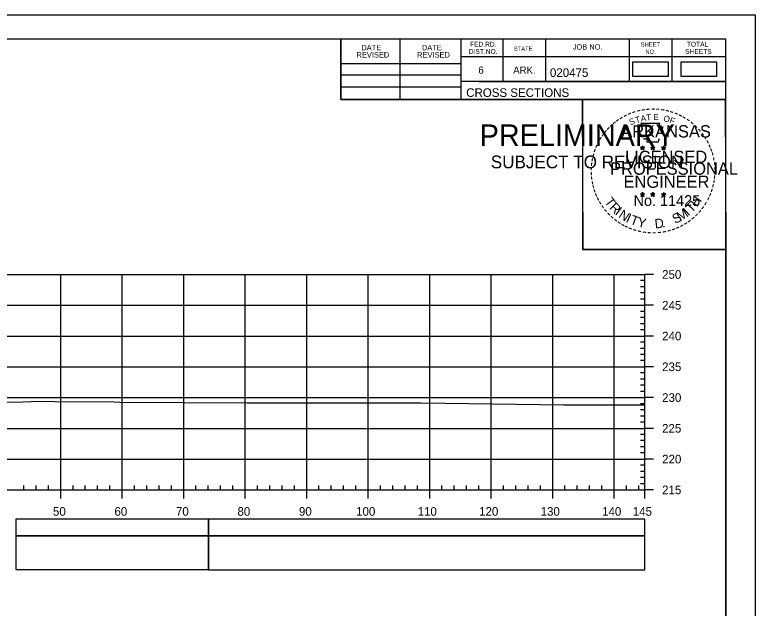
# Model space of a CAD drawing. Extents: x 1386544 to 1388153, y 379785 to 390999.
# Drawn here: x 1386757.4 to 1386877.8, y 384182.2 to 384278.6 of the extents above; entities that cross this region are included whole.
import ezdxf

# ---------------------------------------------------------------- set-up
doc = ezdxf.new("R2010")
doc.units = 0
for name, color, linetype in [('R_Axis', 7, 'Continuous'), ('R_Axis Annot', 7, 'Continuous'), ('R_Border', 7, 'Continuous'), ('R_Border PE', 7, 'Continuous'), ('R_Border Prem', 7, 'Continuous'), ('R_Exist Surface', 7, 'Continuous'), ('R_Grid', 7, 'Continuous'), ('R_No Plot', 7, 'Continuous'), ('R_Striping', 7, 'Continuous'), ('S_SHOULDER', 7, 'Continuous')]:
    doc.layers.add(name, color=color, linetype=linetype)

msp = doc.modelspace()

# ---------------------------------------------------------------- linework, layer by layer
at = {"layer": 'R_Axis'}
for p, q in [((1386859.87, 384201.41), (1386859.87, 384236.41)), ((1386861.27, 384236.41), (1386859.87, 384236.41)), ((1386859.87, 384235.41), (1386859.17, 384235.41)), ((1386859.87, 384234.41), (1386859.17, 384234.41)), ((1386859.87, 384233.41), (1386859.17, 384233.41)), ((1386859.87, 384232.41), (1386859.17, 384232.41)), ((1386861.27, 384231.41), (1386859.87, 384231.41)), ((1386859.87, 384230.41), (1386859.17, 384230.41)), ((1386859.87, 384229.41), (1386859.17, 384229.41)), ((1386859.87, 384228.41), (1386859.17, 384228.41)), ((1386859.87, 384227.41), (1386859.17, 384227.41)), ((1386861.27, 384226.41), (1386859.87, 384226.41)), ((1386859.87, 384225.41), (1386859.17, 384225.41)), ((1386859.87, 384224.41), (1386859.17, 384224.41)), ((1386859.87, 384223.41), (1386859.17, 384223.41)), ((1386859.87, 384222.41), (1386859.17, 384222.41)), ((1386861.27, 384221.41), (1386859.87, 384221.41)), ((1386859.87, 384220.41), (1386859.17, 384220.41)), ((1386859.87, 384219.41), (1386859.17, 384219.41)), ((1386859.87, 384218.41), (1386859.17, 384218.41)), ((1386859.87, 384217.41), (1386859.17, 384217.41)), ((1386861.27, 384216.41), (1386859.87, 384216.41)), ((1386859.87, 384215.41), (1386859.17, 384215.41)), ((1386859.87, 384214.41), (1386859.17, 384214.41)), ((1386859.87, 384213.41), (1386859.17, 384213.41)), ((1386859.87, 384212.41), (1386859.17, 384212.41)), ((1386861.27, 384211.41), (1386859.87, 384211.41)), ((1386859.87, 384210.41), (1386859.17, 384210.41)), ((1386859.87, 384209.41), (1386859.17, 384209.41)), ((1386859.87, 384208.41), (1386859.17, 384208.41)), ((1386859.87, 384207.41), (1386859.17, 384207.41)), ((1386859.87, 384205.41), (1386859.17, 384205.41)), ((1386861.27, 384206.41), (1386859.87, 384206.41)), ((1386859.87, 384204.41), (1386859.17, 384204.41)), ((1386859.87, 384203.41), (1386859.17, 384203.41)), ((1386758.87, 384201.41), (1386758.87, 384202.11)), ((1386760.87, 384201.41), (1386760.87, 384202.11)), ((1386762.87, 384201.41), (1386762.87, 384202.11)), ((1386766.87, 384201.41), (1386766.87, 384202.11)), ((1386768.87, 384201.41), (1386768.87, 384202.11)), ((1386770.87, 384201.41), (1386770.87, 384202.11)), ((1386772.87, 384201.41), (1386772.87, 384202.11)), ((1386776.87, 384201.41), (1386776.87, 384202.11)), ((1386778.87, 384201.41), (1386778.87, 384202.11)), ((1386780.87, 384201.41), (1386780.87, 384202.11)), ((1386782.87, 384201.41), (1386782.87, 384202.11)), ((1386786.87, 384201.41), (1386786.87, 384202.11)), ((1386788.87, 384201.41), (1386788.87, 384202.11)), ((1386790.87, 384201.41), (1386790.87, 384202.11)), ((1386792.87, 384201.41), (1386792.87, 384202.11)), ((1386796.87, 384201.41), (1386796.87, 384202.11)), ((1386798.87, 384201.41), (1386798.87, 384202.11)), ((1386800.87, 384201.41), (1386800.87, 384202.11)), ((1386802.87, 384201.41), (1386802.87, 384202.11)), ((1386806.87, 384201.41), (1386806.87, 384202.11)), ((1386808.87, 384201.41), (1386808.87, 384202.11)), ((1386810.87, 384201.41), (1386810.87, 384202.11)), ((1386812.87, 384201.41), (1386812.87, 384202.11)), ((1386816.87, 384201.41), (1386816.87, 384202.11)), ((1386818.87, 384201.41), (1386818.87, 384202.11)), ((1386820.87, 384201.41), (1386820.87, 384202.11)), ((1386822.87, 384201.41), (1386822.87, 384202.11)), ((1386826.87, 384201.41), (1386826.87, 384202.11)), ((1386828.87, 384201.41), (1386828.87, 384202.11)), ((1386830.87, 384201.41), (1386830.87, 384202.11)), ((1386832.87, 384201.41), (1386832.87, 384202.11)), ((1386836.87, 384201.41), (1386836.87, 384202.11)), ((1386838.87, 384201.41), (1386838.87, 384202.11)), ((1386840.87, 384201.41), (1386840.87, 384202.11)), ((1386842.87, 384201.41), (1386842.87, 384202.11)), ((1386846.87, 384201.41), (1386846.87, 384202.11)), ((1386848.87, 384201.41), (1386848.87, 384202.11)), ((1386850.87, 384201.41), (1386850.87, 384202.11)), ((1386852.87, 384201.41), (1386852.87, 384202.11)), ((1386856.87, 384201.41), (1386856.87, 384202.11)), ((1386858.87, 384201.41), (1386858.87, 384202.11)), ((1386859.87, 384202.41), (1386859.17, 384202.41)), ((1386569.87, 384201.41), (1386859.87, 384201.41)), ((1386764.87, 384200.01), (1386764.87, 384201.41)), ((1386774.87, 384200.01), (1386774.87, 384201.41)), ((1386784.87, 384200.01), (1386784.87, 384201.41)), ((1386794.87, 384200.01), (1386794.87, 384201.41)), ((1386804.87, 384200.01), (1386804.87, 384201.41)), ((1386814.87, 384200.01), (1386814.87, 384201.41)), ((1386824.87, 384200.01), (1386824.87, 384201.41)), ((1386834.87, 384200.01), (1386834.87, 384201.41)), ((1386844.87, 384200.01), (1386844.87, 384201.41)), ((1386854.87, 384200.01), (1386854.87, 384201.41)), ((1386859.87, 384200.01), (1386859.87, 384201.41)), ((1386861.27, 384201.41), (1386859.87, 384201.41))]:
    msp.add_line(p, q, dxfattribs=at)
at = {"layer": 'R_Axis Annot'}
for points in [[(1386788.89, 384193.97), (1386859.87, 384193.97), (1386859.87, 384196.68), (1386788.89, 384196.68)], [(1386788.89, 384188.44), (1386859.87, 384188.44), (1386859.87, 384193.97), (1386788.89, 384193.97)]]:
    msp.add_lwpolyline(points, close=True, dxfattribs=at)
at = {"layer": 'R_Border'}
for p, q in [((1386556.87, 384274.71), (1386873.05, 384274.71)), ((1386810.41, 384264.83), (1386810.41, 384274.71)), ((1386820.09, 384264.83), (1386820.09, 384274.71)), ((1386829.95, 384274.71), (1386829.95, 384264.83)), ((1386836.79, 384274.71), (1386836.79, 384267.77)), ((1386843.73, 384274.71), (1386843.73, 384267.77)), ((1386857.31, 384274.71), (1386857.31, 384267.77)), ((1386864.25, 384274.71), (1386864.25, 384267.77)), ((1386873.05, 384069.25), (1386873.05, 384274.71)), ((1386873.05, 384271.77), (1386829.95, 384271.77)), ((1386873.05, 384271.79), (1386873.05, 384271.79)), ((1386810.41, 384270.69), (1386829.95, 384270.69)), ((1386810.41, 384268.83), (1386829.95, 384268.83)), ((1386810.41, 384266.89), (1386829.95, 384266.89)), ((1386873.05, 384267.77), (1386829.95, 384267.77)), ((1386832.91, 384267.77), (1386873.05, 384267.77)), ((1386873.05, 384264.83), (1386810.41, 384264.83))]:
    msp.add_line(p, q, dxfattribs=at)
at = {"layer": 'R_Border PE'}
for p, q in [((1386859.48, 384257.34), (1386859.44, 384257.08)), ((1386859.48, 384256.97), (1386859.48, 384257.34)), ((1386859.48, 384257.34), (1386859.53, 384257.09)), ((1386861.15, 384257.34), (1386861.11, 384257.08)), ((1386861.15, 384256.97), (1386861.15, 384257.34)), ((1386861.15, 384257.34), (1386861.2, 384257.09)), ((1386862.92, 384257.32), (1386862.88, 384257.07)), ((1386862.92, 384256.96), (1386862.92, 384257.32)), ((1386862.92, 384257.32), (1386862.97, 384257.07)), ((1386859.14, 384257.08), (1386859.48, 384256.97)), ((1386859.14, 384257.08), (1386859.39, 384257.04)), ((1386859.14, 384257.08), (1386859.37, 384256.96)), ((1386859.27, 384256.67), (1386859.48, 384256.97)), ((1386859.27, 384256.67), (1386859.39, 384256.92)), ((1386859.27, 384256.67), (1386859.48, 384256.89)), ((1386859.83, 384257.08), (1386859.48, 384256.97)), ((1386859.7, 384256.67), (1386859.48, 384256.97)), ((1386859.7, 384256.67), (1386859.48, 384256.89)), ((1386859.83, 384257.08), (1386859.55, 384257.03)), ((1386859.7, 384256.67), (1386859.56, 384256.96)), ((1386859.83, 384257.08), (1386859.63, 384256.98)), ((1386860.81, 384257.08), (1386861.15, 384256.97)), ((1386860.81, 384257.08), (1386861.06, 384257.04)), ((1386860.81, 384257.08), (1386861.04, 384256.96)), ((1386860.94, 384256.67), (1386861.15, 384256.97)), ((1386860.94, 384256.67), (1386861.06, 384256.92)), ((1386860.94, 384256.67), (1386861.15, 384256.89)), ((1386861.5, 384257.08), (1386861.15, 384256.97)), ((1386861.37, 384256.67), (1386861.15, 384256.97)), ((1386861.37, 384256.67), (1386861.15, 384256.89)), ((1386861.5, 384257.08), (1386861.22, 384257.03)), ((1386861.37, 384256.67), (1386861.23, 384256.96)), ((1386861.5, 384257.08), (1386861.3, 384256.98)), ((1386862.57, 384257.07), (1386862.92, 384256.96)), ((1386862.57, 384257.07), (1386862.82, 384257.02)), ((1386862.57, 384257.07), (1386862.81, 384256.95)), ((1386862.7, 384256.66), (1386862.92, 384256.96)), ((1386862.7, 384256.66), (1386862.83, 384256.91)), ((1386862.7, 384256.66), (1386862.92, 384256.88)), ((1386863.27, 384257.07), (1386862.92, 384256.96)), ((1386863.13, 384256.66), (1386862.92, 384256.96)), ((1386863.13, 384256.66), (1386862.92, 384256.88)), ((1386863.27, 384257.07), (1386862.98, 384257.02)), ((1386863.13, 384256.66), (1386862.99, 384256.95)), ((1386863.27, 384257.07), (1386863.06, 384256.97)), ((1386859.13, 384249.51), (1386859.48, 384249.4)), ((1386859.13, 384249.51), (1386859.38, 384249.46)), ((1386859.13, 384249.51), (1386859.37, 384249.39)), ((1386859.26, 384249.1), (1386859.48, 384249.4)), ((1386859.26, 384249.1), (1386859.39, 384249.34)), ((1386859.26, 384249.1), (1386859.48, 384249.32)), ((1386859.48, 384249.76), (1386859.44, 384249.51)), ((1386859.48, 384249.4), (1386859.48, 384249.76)), ((1386859.48, 384249.76), (1386859.53, 384249.51)), ((1386859.83, 384249.51), (1386859.48, 384249.4)), ((1386859.69, 384249.1), (1386859.48, 384249.4)), ((1386859.69, 384249.1), (1386859.48, 384249.31)), ((1386859.83, 384249.51), (1386859.54, 384249.46)), ((1386859.69, 384249.1), (1386859.56, 384249.39)), ((1386859.83, 384249.51), (1386859.62, 384249.41)), ((1386860.8, 384249.51), (1386861.15, 384249.4)), ((1386860.8, 384249.51), (1386861.05, 384249.46)), ((1386860.8, 384249.51), (1386861.04, 384249.39)), ((1386860.93, 384249.1), (1386861.15, 384249.4)), ((1386860.93, 384249.1), (1386861.06, 384249.34)), ((1386860.93, 384249.1), (1386861.15, 384249.32)), ((1386861.15, 384249.76), (1386861.11, 384249.51)), ((1386861.15, 384249.4), (1386861.15, 384249.76)), ((1386861.15, 384249.76), (1386861.2, 384249.51)), ((1386861.5, 384249.51), (1386861.15, 384249.4)), ((1386861.36, 384249.1), (1386861.15, 384249.4)), ((1386861.36, 384249.1), (1386861.15, 384249.31)), ((1386861.5, 384249.51), (1386861.21, 384249.46)), ((1386861.36, 384249.1), (1386861.23, 384249.39)), ((1386861.5, 384249.51), (1386861.29, 384249.41)), ((1386862.57, 384249.5), (1386862.92, 384249.39)), ((1386862.57, 384249.5), (1386862.82, 384249.45)), ((1386862.57, 384249.5), (1386862.8, 384249.38)), ((1386862.7, 384249.09), (1386862.92, 384249.39)), ((1386862.7, 384249.09), (1386862.83, 384249.33)), ((1386862.7, 384249.09), (1386862.91, 384249.31)), ((1386862.92, 384249.75), (1386862.88, 384249.5)), ((1386863.13, 384249.09), (1386862.91, 384249.3)), ((1386862.92, 384249.39), (1386862.92, 384249.75)), ((1386862.92, 384249.75), (1386862.97, 384249.5)), ((1386863.26, 384249.5), (1386862.92, 384249.39)), ((1386863.13, 384249.09), (1386862.92, 384249.39)), ((1386863.26, 384249.5), (1386862.98, 384249.45)), ((1386863.13, 384249.09), (1386862.99, 384249.38)), ((1386863.26, 384249.5), (1386863.06, 384249.4))]:
    msp.add_line(p, q, dxfattribs=at)
for points in [[(1386859.18, 384260.96), (1386859.45, 384260.13)], [(1386862.69, 384260.04), (1386862.83, 384260.32), (1386862.14, 384260.3), (1386862.29, 384260.96), (1386859.18, 384260.96)], [(1386859.67, 384258.54), (1386859.67, 384258.45), (1386860.23, 384258.43), (1386860.18, 384257.96), (1386862.05, 384257.96), (1386862.25, 384258.49)], [(1386859.48, 384257.34), (1386859.7, 384256.67), (1386859.14, 384257.08), (1386859.83, 384257.08), (1386859.27, 384256.67), (1386859.48, 384257.34)], [(1386861.15, 384257.34), (1386861.37, 384256.67), (1386860.81, 384257.08), (1386861.5, 384257.08), (1386860.94, 384256.67), (1386861.15, 384257.34)], [(1386862.92, 384257.32), (1386863.13, 384256.66), (1386862.57, 384257.07), (1386863.27, 384257.07), (1386862.7, 384256.66), (1386862.92, 384257.32)], [(1386859.48, 384249.76), (1386859.69, 384249.1), (1386859.13, 384249.51), (1386859.83, 384249.51), (1386859.26, 384249.1), (1386859.48, 384249.76)], [(1386861.15, 384249.76), (1386861.36, 384249.1), (1386860.8, 384249.51), (1386861.5, 384249.51), (1386860.93, 384249.1), (1386861.15, 384249.76)], [(1386862.92, 384249.75), (1386863.13, 384249.09), (1386862.57, 384249.5), (1386863.26, 384249.5), (1386862.7, 384249.09), (1386862.92, 384249.75)]]:
    msp.add_lwpolyline(points, dxfattribs=at)
for centre, radius in [((1386859.48, 384256.97), 0.172), ((1386859.48, 384256.97), 0.145), ((1386861.15, 384256.97), 0.172), ((1386861.15, 384256.97), 0.145), ((1386862.92, 384256.96), 0.172), ((1386859.48, 384256.97), 0.116), ((1386859.48, 384256.97), 0.0991), ((1386859.48, 384256.97), 0.0747), ((1386859.48, 384256.97), 0.0495), ((1386859.48, 384256.97), 0.0296), ((1386861.15, 384256.97), 0.116), ((1386861.15, 384256.97), 0.0991), ((1386861.15, 384256.97), 0.0747), ((1386861.15, 384256.97), 0.0495), ((1386861.15, 384256.97), 0.0296), ((1386862.92, 384256.96), 0.145), ((1386862.92, 384256.96), 0.116), ((1386862.92, 384256.96), 0.0991), ((1386862.92, 384256.96), 0.0747), ((1386862.92, 384256.96), 0.0495), ((1386862.92, 384256.96), 0.0296), ((1386859.48, 384249.4), 0.172), ((1386859.48, 384249.4), 0.145), ((1386859.48, 384249.4), 0.116), ((1386859.48, 384249.4), 0.0991), ((1386859.48, 384249.4), 0.0747), ((1386859.48, 384249.4), 0.0495), ((1386859.48, 384249.4), 0.0296), ((1386861.15, 384249.4), 0.172), ((1386861.15, 384249.4), 0.145), ((1386861.15, 384249.4), 0.116), ((1386861.15, 384249.4), 0.0991), ((1386861.15, 384249.4), 0.0747), ((1386861.15, 384249.4), 0.0495), ((1386861.15, 384249.4), 0.0296), ((1386862.92, 384249.39), 0.172), ((1386862.92, 384249.39), 0.145), ((1386862.92, 384249.39), 0.116), ((1386862.92, 384249.39), 0.0991), ((1386862.92, 384249.39), 0.0747), ((1386862.92, 384249.39), 0.0495), ((1386862.92, 384249.39), 0.0296)]:
    msp.add_circle(centre, radius, dxfattribs=at)
at = {"layer": 'R_Exist Surface'}
msp.add_lwpolyline([(1386750.38, 384215.56), (1386758.7, 384215.74), (1386761.41, 384215.8), (1386763.89, 384215.79), (1386773.59, 384215.7), (1386774.5, 384215.68), (1386795.26, 384215.58), (1386812.09, 384215.56), (1386816.68, 384215.57), (1386823.44, 384215.54), (1386846.67, 384215.25), (1386852.54, 384215.24), (1386859.87, 384215.25)], dxfattribs=at)
at = {"layer": 'R_Grid'}
for p, q in [((1386569.87, 384236.41), (1386859.87, 384236.41)), ((1386764.87, 384201.41), (1386764.87, 384236.41)), ((1386774.87, 384201.41), (1386774.87, 384236.41)), ((1386784.87, 384201.41), (1386784.87, 384236.41)), ((1386794.87, 384201.41), (1386794.87, 384236.41)), ((1386804.87, 384201.41), (1386804.87, 384236.41)), ((1386814.87, 384201.41), (1386814.87, 384236.41)), ((1386824.87, 384201.41), (1386824.87, 384236.41)), ((1386834.87, 384201.41), (1386834.87, 384236.41)), ((1386844.87, 384201.41), (1386844.87, 384236.41)), ((1386854.87, 384201.41), (1386854.87, 384236.41)), ((1386859.87, 384201.41), (1386859.87, 384236.41)), ((1386569.87, 384231.41), (1386859.87, 384231.41)), ((1386569.87, 384226.41), (1386859.87, 384226.41)), ((1386569.87, 384221.41), (1386859.87, 384221.41)), ((1386569.87, 384216.41), (1386859.87, 384216.41)), ((1386569.87, 384211.41), (1386859.87, 384211.41)), ((1386569.87, 384206.41), (1386859.87, 384206.41)), ((1386569.87, 384201.41), (1386859.87, 384201.41))]:
    msp.add_line(p, q, dxfattribs=at)
at = {"layer": 'R_No Plot'}
for p, q in [((1386544.47, 384278.6), (1386877.8, 384278.6)), ((1386849.08, 384242.37), (1386849.08, 384242.37))]:
    msp.add_line(p, q, dxfattribs=at)
for points in [[(1386544.46, 384278.6), (1386877.8, 384278.6), (1386877.8, 384065.26), (1386544.46, 384065.26)], [(1386790.79, 384274.71), (1386810.41, 384274.71), (1386810.41, 384264.83), (1386826.52, 384264.83), (1386849.72, 384264.83), (1386849.72, 384240.49), (1386873.05, 384240.49), (1386873.05, 384069.25), (1386556.87, 384069.25), (1386556.87, 384274.71)], [(1386849.72, 384264.83), (1386872.93, 384264.83), (1386873.05, 384240.49), (1386849.84, 384240.49)]]:
    msp.add_lwpolyline(points, close=True, dxfattribs=at)
at = {"layer": 'R_Striping'}
for points in [[(1386757.55, 384193.97), (1386788.89, 384193.97), (1386788.89, 384196.68), (1386757.55, 384196.68)], [(1386757.55, 384188.45), (1386788.89, 384188.45), (1386788.89, 384193.97), (1386757.55, 384193.97)]]:
    msp.add_lwpolyline(points, close=True, dxfattribs=at)
at = {"layer": 'S_SHOULDER'}
for points in [[(1386857.86, 384268.61), (1386863.7, 384268.61), (1386863.7, 384270.92), (1386857.86, 384270.92)], [(1386865.73, 384268.61), (1386871.57, 384268.61), (1386871.57, 384270.92), (1386865.73, 384270.92)]]:
    msp.add_lwpolyline(points, close=True, dxfattribs=at)

# ---------------------------------------------------------------- texts
at = {"layer": 'R_Axis Annot'}
for s, p in [('250', (1386862.67, 384235.71)), ('245', (1386862.67, 384230.71)), ('240', (1386862.67, 384225.71)), ('235', (1386862.67, 384220.71)), ('230', (1386862.67, 384215.71)), ('225', (1386862.67, 384210.71)), ('220', (1386862.67, 384205.71)), ('215', (1386862.67, 384200.71)), ('50', (1386763.61, 384197.21)), ('60', (1386773.61, 384197.21)), ('70', (1386783.61, 384197.21)), ('80', (1386793.61, 384197.21)), ('90', (1386803.61, 384197.21)), ('100', (1386812.91, 384197.21)), ('110', (1386822.91, 384197.21)), ('120', (1386832.91, 384197.21)), ('130', (1386842.91, 384197.21)), ('140', (1386852.91, 384197.21)), ('145', (1386857.9, 384197.21))]:
    msp.add_text(s, height=1.4, dxfattribs=at).set_placement(p)
at = {"layer": 'R_Border'}
for s, height, p in [('FED.RD.', 0.782, (1386831.43, 384273.43)), ('SHEET', 0.684, (1386859.17, 384273.43)), ('TOTAL', 0.782, (1386866.69, 384273.43)), ('DATE', 0.879, (1386813.75, 384272.84)), ('DATE', 0.879, (1386823.61, 384272.84)), ('DIST.NO.', 0.782, (1386831.23, 384272.25)), ('STATE', 0.684, (1386838.55, 384272.75)), ('JOB NO.', 0.879, (1386848.13, 384272.95)), ('NO.', 0.684, (1386859.95, 384272.25)), ('SHEETS', 0.782, (1386866.41, 384272.25)), ('REVISED', 0.879, (1386812.97, 384271.66)), ('REVISED', 0.879, (1386822.83, 384271.66)), ('6', 1.17, (1386832.79, 384269.03)), ('ARK.', 1.172, (1386838.45, 384269.03)), ('020475', 1.4, (1386844.43, 384268.51)), ('CROSS SECTIONS', 1.4, (1386830.81, 384265.26))]:
    msp.add_text(s, height=height, rotation=360, dxfattribs=at).set_placement(p)
at = {"layer": 'R_Border PE'}
for s, height, rotation, p in [('-', 1.6, 13.6301, (1386858.67, 384262.33)), ('-', 1.6, 10.2193, (1386859.35, 384262.49)), ('-', 1.6, 5.8968, (1386860.08, 384262.6)), ('-', 1.6, 0.1862, (1386860.85, 384262.67)), ('-', 1.6, 357.743, (1386861.58, 384262.66)), ('-', 1.6, 352.1617, (1386862.32, 384262.6)), ('-', 1.6, 347.2049, (1386863.04, 384262.49)), ('-', 1.6, 34.0636, (1386856.06, 384261.13)), ('-', 1.6, 28.7918, (1386856.66, 384261.5)), ('-', 1.6, 24.3072, (1386857.29, 384261.82)), ('-', 1.6, 19.1761, (1386857.92, 384262.09)), ('T', 1, 16.4036, (1386858.45, 384260.97)), ('A', 1, 11.2132, (1386859.27, 384261.22)), ('T', 1, 6.0228, (1386860.12, 384261.39)), ('E', 1, 0.8323, (1386861.23, 384261.5)), ('O', 1, 350.4515, (1386862.83, 384261.29)), ('F', 1, 340.0707, (1386863.78, 384261.06)), ('-', 1.6, 342.3362, (1386863.67, 384262.33)), ('-', 1.6, 337.8551, (1386864.41, 384262.11)), ('-', 1.6, 334.1211, (1386865.04, 384261.84)), ('-', 1.6, 329.6409, (1386865.62, 384261.56)), ('-', 1.6, 42.9622, (1386854.57, 384259.94)), ('-', 1.6, 38.9507, (1386855.01, 384260.36)), ('-', 1.6, 36.2317, (1386855.48, 384260.74)), ('S', 1, 21.594, (1386857.53, 384260.64)), ('-', 1.6, 325.8627, (1386866.26, 384261.2)), ('-', 1.6, 320.5297, (1386866.87, 384260.77)), ('-', 1.6, 50.6142, (1386853.72, 384258.98)), ('-', 1.6, 48.423, (1386854.13, 384259.46)), ('ARKANSAS', 2, 360, (1386856.03, 384258.67)), ('-', 1.6, 315.5786, (1386867.47, 384260.28)), ('-', 1.6, 309.8797, (1386868.04, 384259.73)), ('-', 1.6, 58.0706, (1386852.98, 384257.88)), ('-', 1.6, 54.2325, (1386853.31, 384258.41)), ('-', 1.6, 306.6522, (1386868.57, 384259.13)), ('-', 1.4, 303.6753, (1386869.05, 384258.56)), ('-', 1.6, 67.7743, (1386852.41, 384256.66)), ('-', 1.6, 62.8713, (1386852.67, 384257.27)), ('-', 1.6, 299.6684, (1386869.37, 384257.95)), ('-', 1.6, 294.6628, (1386869.69, 384257.34)), ('-', 1.6, 75.461, (1386852, 384255.31)), ('-', 1.6, 72.3945, (1386852.19, 384256.03)), ('LICENSED', 2, 360, (1386856.63, 384254.52)), ('DWB', 0.01, 360, (1386859.47, 384256.97)), ('DWB', 0.01, 360, (1386861.14, 384256.97)), ('DWB', 0.01, 360, (1386862.91, 384256.95)), ('-', 1.6, 290.5728, (1386869.95, 384256.77)), ('-', 1.6, 285.1233, (1386870.19, 384256.19)), ('-', 1.6, 81.2013, (1386851.86, 384254.6)), ('-', 1.6, 280.5493, (1386870.39, 384255.44)), ('-', 1.6, 89.0622, (1386851.76, 384253.21)), ('-', 1.6, 85.1863, (1386851.79, 384253.91)), ('PROFESSIONAL', 2, 360, (1386854.2, 384252.62)), ('-', 1.6, 276.5962, (1386870.55, 384254.68)), ('-', 1.6, 274.3301, (1386870.61, 384253.95)), ('-', 1.6, 94.1959, (1386851.8, 384252.48)), ('-', 1.6, 98.9479, (1386851.87, 384251.82)), ('ENGINEER', 2, 360, (1386856.39, 384250.49)), ('-', 1.6, 263.5172, (1386870.62, 384252.66)), ('-', 1.6, 269.9407, (1386870.64, 384253.32)), ('-', 1.6, 101.7149, (1386852.01, 384251.08)), ('-', 1.6, 255.7626, (1386870.44, 384251.32)), ('-', 1.6, 260.9953, (1386870.55, 384252)), ('-', 1.6, 105.4578, (1386852.17, 384250.49)), ('-', 1.6, 109.0874, (1386852.38, 384249.86)), ('-', 1.6, 252.8681, (1386870.26, 384250.6)), ('-', 1.6, 114.0643, (1386852.64, 384249.26)), ('-', 1.6, 115.7289, (1386852.94, 384248.64)), ('T', 1.54, 306.0406, (1386853.24, 384248.24)), ('No. 11425', 1.757, 360, (1386858.02, 384247.54)), ('DWB', 0.01, 360, (1386859.47, 384249.39)), ('DWB', 0.01, 360, (1386861.14, 384249.39)), ('DWB', 0.01, 360, (1386862.9, 384249.38)), ('H', 1.54, 54.6088, (1386868.36, 384247.27)), ('-', 1.6, 244.6197, (1386869.78, 384249.3)), ('-', 1.6, 247.8887, (1386870.04, 384249.93)), ('-', 1.6, 120.4471, (1386853.3, 384248.06)), ('-', 1.6, 125.8934, (1386853.7, 384247.5)), ('R', 1.54, 314.005, (1386854, 384247.19)), ('T', 1.54, 46.6444, (1386867.47, 384246.33)), ('-', 1.6, 233.8452, (1386868.98, 384247.9)), ('-', 1.6, 239.0712, (1386869.38, 384248.55)), ('-', 1.6, 130.7181, (1386854.16, 384246.94)), ('-', 1.6, 134.2238, (1386854.68, 384246.4)), ('I', 1.54, 321.9694, (1386854.9, 384246.26)), ('N', 1.54, 326.5002, (1386855.47, 384245.78)), ('I', 1.54, 335.3603, (1386856.68, 384245)), ('S', 1.54, 26.9312, (1386864.79, 384244.6)), ('M', 1.54, 32.6563, (1386865.62, 384245)), ('I', 1.54, 42.1136, (1386866.91, 384245.85)), ('-', 1.6, 225.7653, (1386868.07, 384246.77)), ('-', 1.6, 231.2538, (1386868.55, 384247.33)), ('-', 1.6, 138.9338, (1386855.21, 384245.94)), ('-', 1.6, 144.6463, (1386855.76, 384245.53)), ('T', 1.54, 339.8912, (1386857.34, 384244.67)), ('Y', 1.54, 347.8556, (1386858.56, 384244.23)), ('D', 1.54, 6.3969, (1386861.54, 384243.87)), ('-', 1.6, 215.7363, (1386867, 384245.79)), ('-', 1.6, 221.0851, (1386867.55, 384246.26)), ('-', 1.6, 148.0898, (1386856.32, 384245.16)), ('-', 1.6, 151.5704, (1386856.9, 384244.83)), ('-', 1.6, 154.6002, (1386857.42, 384244.59)), ('-', 1.6, 158.5612, (1386858.05, 384244.33)), ('.', 1.54, 13.7642, (1386862.73, 384243.99)), ('-', 1.6, 200.7184, (1386864.66, 384244.46)), ('-', 1.6, 204.2516, (1386865.28, 384244.73)), ('-', 1.6, 207.3568, (1386865.91, 384245.05)), ('-', 1.6, 212.2491, (1386866.47, 384245.4)), ('-', 1.6, 162.7983, (1386858.73, 384244.12)), ('-', 1.6, 167.5555, (1386859.45, 384243.96)), ('-', 1.6, 173.1155, (1386860.22, 384243.85)), ('-', 1.6, 176.5183, (1386860.97, 384243.79)), ('-', 1.6, 181.5918, (1386861.71, 384243.81)), ('-', 1.6, 185.8167, (1386862.52, 384243.89)), ('-', 1.6, 191.2858, (1386863.26, 384244.02)), ('-', 1.6, 195.4743, (1386863.99, 384244.22))]:
    msp.add_text(s, height=height, rotation=rotation, dxfattribs=at).set_placement(p)
at = {"layer": 'R_Border Prem'}
for s, height, p in [('PRELIMINARY', 3.5, (1386833, 384257.29)), ('DWB', 0.01, (1386833.75, 384259.14)), ('SUBJECT TO REVISION', 2.0751, (1386834.81, 384253.66))]:
    msp.add_text(s, height=height, rotation=360, dxfattribs=at).set_placement(p)

doc.saveas('drawing.dxf')
